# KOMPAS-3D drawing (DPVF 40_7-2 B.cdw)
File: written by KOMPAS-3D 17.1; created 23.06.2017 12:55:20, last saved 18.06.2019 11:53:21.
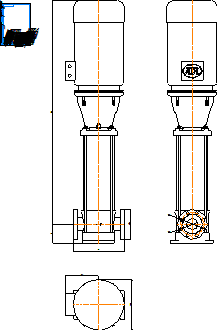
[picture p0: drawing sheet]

Sheet 1: A4, portrait

Title block, sheet 1: name: DPVF 40_7-2 B; material: Внимание! Данный продукт является объектом авторского права ООО «Торговый Дом АДЛ». / Запрещается изменение, копирование, распространение / (в том числе путем копирования на другие сайты и ресурсы в Интернете) / или любое иное использование информации и объектов без предварительного / согласия правообладателя (ООО «Торговый Дом АДЛ»).; scale: 1:1; sheets: 1; organisation: ООО "Торговый дом АДЛ"; sheet format: A4; stored path: C:\Клочков АВ\Насосы\DP PAMS\DPVF 40\Компас 2d\DPVF 40_7-2 B.cdw

Views: Спереди 1
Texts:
  Клочков АВ
  ООО АДЛ ГРУПП
Dimensions and other numbers on the sheet: 365; 234; 360; 209,6; 1583,5; 140; 168,1; 76,2; 1:1; 1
